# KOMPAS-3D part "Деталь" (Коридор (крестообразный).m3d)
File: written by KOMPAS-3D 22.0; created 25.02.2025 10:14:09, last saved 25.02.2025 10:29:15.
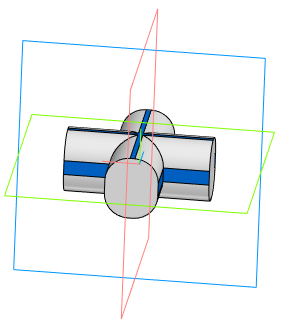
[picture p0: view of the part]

Document properties: Автор: Пользователь Windows; Полное имя файла: C:\Users\Student\Documents\Картошечка\База Сабнатика\Коридор\Коридор (крестообразный).m3d

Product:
- Part/product: Деталь
    Масса: 0.04792

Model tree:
1. Эскиз:1
2. Элемент выдавливания:1
     Расстояние 1 = 30
3. Эскиз:2
4. Элемент выдавливания:2
     Расстояние 1 = 30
